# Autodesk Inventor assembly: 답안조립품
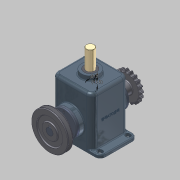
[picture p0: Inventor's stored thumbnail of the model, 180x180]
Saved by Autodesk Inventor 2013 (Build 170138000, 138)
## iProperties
Created: 2015-03
Part Number: 답안조립품
Document SubType Name: Assembly
Designer: kb146
Mass: 8578.99 g
Surface Area: 4386.43 cm^2
Volume: 1982.5 cm^3
Density: 4.32735 g/cm^3
Author: kb146
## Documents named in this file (15)
- C:\Users\kb146\Desktop\350305V1045\답안조립품.iam
- C:\Users\kb146\Desktop\350305V1045\본체.ipt
- C:\Users\kb146\Desktop\350305V1045\커버.ipt
- C:\Users\kb146\Desktop\350305V1045\베어링 6205.ipt
- C:\Users\kb146\Desktop\350305V1045\편심축.ipt
- C:\Users\kb146\Desktop\350305V1045\멈춤링.ipt
- C:\Users\kb146\Desktop\350305V1045\M4x0.5.ipt
- C:\Users\kb146\Desktop\350305V1045\오일실.ipt
- C:\Users\kb146\Desktop\350305V1045\키 8x8.ipt
- C:\Users\kb146\Desktop\350305V1045\V-벨트풀리.ipt
- C:\Users\kb146\Desktop\350305V1045\멈춤나사 M5x0.5.ipt
- C:\Users\kb146\Desktop\350305V1045\체인 스프로킷.ipt
- C:\Users\kb146\Desktop\350305V1045\부시.ipt
- C:\Users\kb146\Desktop\350305V1045\슬라이드.ipt
- C:\Users\kb146\Desktop\350305V1045\가변스프링.ipt
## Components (9 placed, 4 different names)
1. V-벨트풀리:1 — 각도:3
2. 5-체인 스프로킷:1 — 각도:4
3. 가변스프링:1
4. M4x0.5:1
5. M4x0.5:2
6. M4x0.5:3
7. M4x0.5:4
8. M4x0.5:5
9. M4x0.5:6
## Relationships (2: Angle 2)
- 각도:3 [Angle]: V-벨트풀리:1
- 각도:4 [Angle]: 5-체인 스프로킷:1
